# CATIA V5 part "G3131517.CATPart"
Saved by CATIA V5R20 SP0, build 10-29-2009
Part number: G3131517
Revision: 3
Definition: design
Nomenclature: G3131517
Source: made
Description: NOT SPECIFIED
Bounding box of the stored display mesh (mm): x -9 to 17, y -12.31 to 12.31, z -12.5 to 12.5
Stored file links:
  C:\Users\Raffaele\Desktop\3D X SITO CF\BOLEX\24-BUSH REF 313\G3131517.CATPart
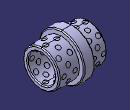
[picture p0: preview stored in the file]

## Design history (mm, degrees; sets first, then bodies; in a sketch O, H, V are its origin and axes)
Body1 "MANIFOLD_SOLID_BREP #6605" (main body)
  Solid1: solid without history
Body2 "MANIFOLD_SOLID_BREP #6748"
  Solid2: solid without history
Body3 "MANIFOLD_SOLID_BREP #6891"
  Solid3: solid without history
Body4 "MANIFOLD_SOLID_BREP #7034"
  Solid4: solid without history
Body5 "MANIFOLD_SOLID_BREP #7177"
  Solid5: solid without history
Body6 "MANIFOLD_SOLID_BREP #7322"
  Solid6: solid without history
Body7 "MANIFOLD_SOLID_BREP #7467"
  Solid7: solid without history
Body8 "MANIFOLD_SOLID_BREP #7612"
  Solid8: solid without history
Body9 "MANIFOLD_SOLID_BREP #7757"
  Solid9: solid without history
Body10 "MANIFOLD_SOLID_BREP #7902"
  Solid10: solid without history
Body11 "MANIFOLD_SOLID_BREP #8047"
  Solid11: solid without history
Body12 "MANIFOLD_SOLID_BREP #8192"
  Solid12: solid without history
Body13 "MANIFOLD_SOLID_BREP #8337"
  Solid13: solid without history
Body14 "MANIFOLD_SOLID_BREP #8482"
  Solid14: solid without history
Body15 "MANIFOLD_SOLID_BREP #8627"
  Solid15: solid without history
Body16 "MANIFOLD_SOLID_BREP #8772"
  Solid16: solid without history
Body17 "MANIFOLD_SOLID_BREP #8917"
  Solid17: solid without history
Body18 "MANIFOLD_SOLID_BREP #9062"
  Solid18: solid without history
Body19 "MANIFOLD_SOLID_BREP #9207"
  Solid19: solid without history
Body20 "MANIFOLD_SOLID_BREP #9351"
  Solid20: solid without history
Body21 "MANIFOLD_SOLID_BREP #9494"
  Solid21: solid without history
Body22 "MANIFOLD_SOLID_BREP #9639"
  Solid22: solid without history
Body23 "MANIFOLD_SOLID_BREP #9783"
  Solid23: solid without history
Body24 "MANIFOLD_SOLID_BREP #9926"
  Solid24: solid without history
Body25 "MANIFOLD_SOLID_BREP #10071"
  Solid25: solid without history
Body26 "MANIFOLD_SOLID_BREP #10216"
  Solid26: solid without history
Body27 "MANIFOLD_SOLID_BREP #10361"
  Solid27: solid without history
Body28 "MANIFOLD_SOLID_BREP #10506"
  Solid28: solid without history
Body29 "MANIFOLD_SOLID_BREP #10651"
  Solid29: solid without history
Body30 "MANIFOLD_SOLID_BREP #10796"
  Solid30: solid without history
Body31 "MANIFOLD_SOLID_BREP #10941"
  Solid31: solid without history
Body32 "MANIFOLD_SOLID_BREP #11086"
  Solid32: solid without history
Body33 "MANIFOLD_SOLID_BREP #11231"
  Solid33: solid without history
Body34 "MANIFOLD_SOLID_BREP #11376"
  Solid34: solid without history
Body35 "MANIFOLD_SOLID_BREP #11521"
  Solid35: solid without history
Body36 "MANIFOLD_SOLID_BREP #11666"
  Solid36: solid without history
Body37 "MANIFOLD_SOLID_BREP #11811"
  Solid37: solid without history
Body38 "MANIFOLD_SOLID_BREP #11954"
  Solid38: solid without history
Body39 "MANIFOLD_SOLID_BREP #12097"
  Solid39: solid without history
Body40 "MANIFOLD_SOLID_BREP #12240"
  Solid40: solid without history
Body41 "MANIFOLD_SOLID_BREP #12383"
  Solid41: solid without history
Body42 "MANIFOLD_SOLID_BREP #12528"
  Solid42: solid without history
Body43 "MANIFOLD_SOLID_BREP #12673"
  Solid43: solid without history
Body44 "MANIFOLD_SOLID_BREP #12817"
  Solid44: solid without history
Body45 "MANIFOLD_SOLID_BREP #12960"
  Solid45: solid without history
Body46 "MANIFOLD_SOLID_BREP #13105"
  Solid46: solid without history
Body47 "MANIFOLD_SOLID_BREP #13249"
  Solid47: solid without history
Body48 "MANIFOLD_SOLID_BREP #13392"
  Solid48: solid without history
Body49 "MANIFOLD_SOLID_BREP #13537"
  Solid49: solid without history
